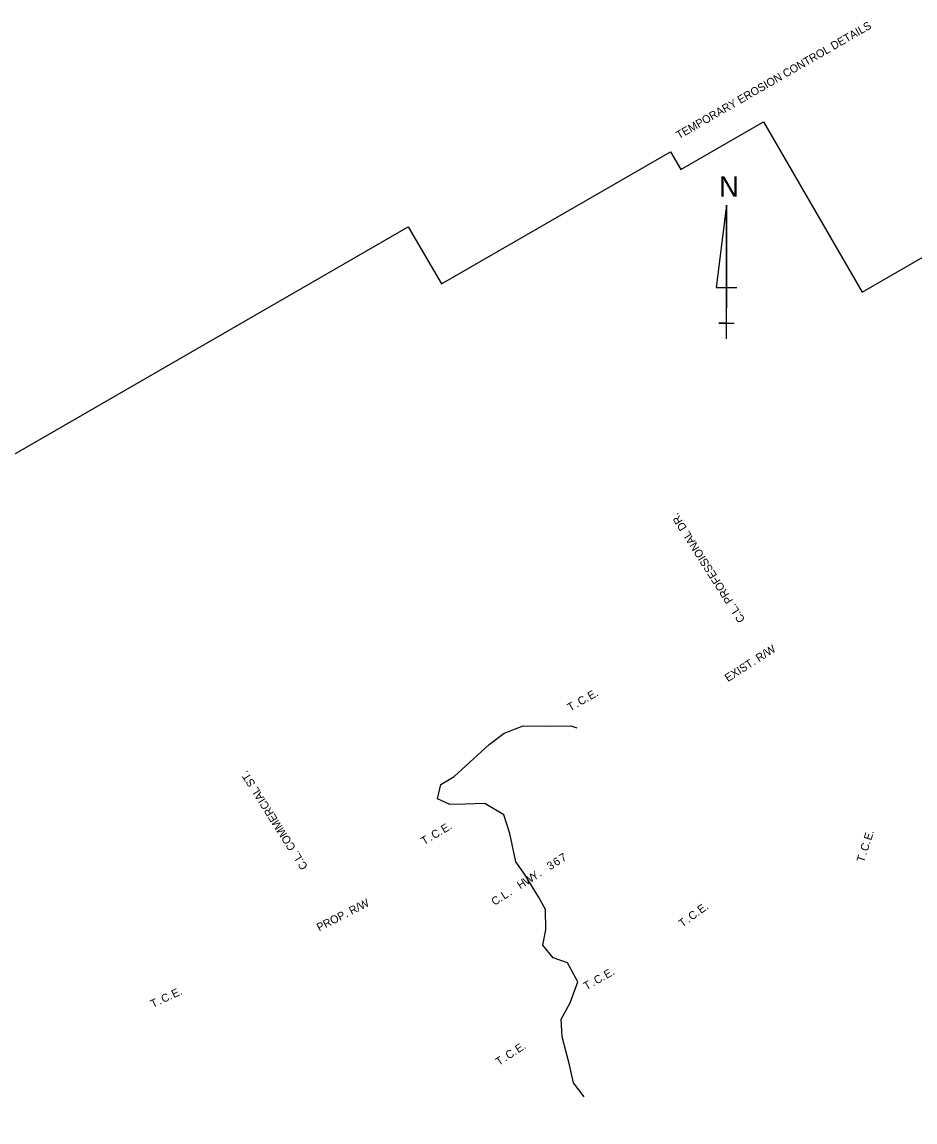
# Model space of a CAD drawing. Extents: x 1293524 to 1295623, y 222963 to 224839.
# Drawn here: x 1294272 to 1294941, y 223794 to 224618 of the extents above; entities that cross this region are included whole.
import ezdxf

# ---------------------------------------------------------------- set-up
doc = ezdxf.new("R2010")
doc.units = 0
for name, color, linetype in [('10Tan10', 7, 'Continuous'), ('Default', 7, 'Continuous'), ('G-No Plot-Border-1', 7, 'Continuous'), ('Level 1', 7, 'Continuous'), ('R_Draft', 7, 'Continuous'), ('S_TREE', 7, 'Continuous')]:
    doc.layers.add(name, color=color, linetype=linetype)

msp = doc.modelspace()

# ---------------------------------------------------------------- linework, layer by layer
at = {"layer": 'G-No Plot-Border-1'}
msp.add_lwpolyline([(1294045.04, 222962.86), (1293523.88, 223865.53), (1294561.39, 224464.54), (1294586.16, 224421.63), (1294757.85, 224520.75), (1294765.6, 224507.33), (1294827.61, 224543.13), (1294901.36, 224415.39), (1295011.78, 224479.14), (1295426.66, 223760.54)], close=True, dxfattribs=at)
msp.add_lwpolyline([(1294045.04, 222962.86), (1293523.88, 223865.53), (1294561.39, 224464.54), (1294586.16, 224421.63), (1294757.85, 224520.75), (1294765.6, 224507.33), (1294827.61, 224543.13), (1294901.36, 224415.39), (1295011.78, 224479.14), (1295426.66, 223760.54)], close=True, dxfattribs=at)
msp.add_lwpolyline([(1294045.04, 222962.86), (1293523.88, 223865.53), (1294561.39, 224464.54), (1294586.16, 224421.63), (1294757.85, 224520.75), (1294765.6, 224507.33), (1294827.61, 224543.13), (1294901.36, 224415.39), (1295011.78, 224479.14), (1295426.66, 223760.54)], close=True, dxfattribs=at)
msp.add_lwpolyline([(1294045.04, 222962.86), (1293523.88, 223865.53), (1294561.39, 224464.54), (1294586.16, 224421.63), (1294757.85, 224520.75), (1294765.6, 224507.33), (1294827.61, 224543.13), (1294901.36, 224415.39), (1295011.78, 224479.14), (1295426.66, 223760.54)], close=True, dxfattribs=at)
at = {"layer": 'Level 1'}
for p, q in [((1294799.86, 224480.59), (1294792.16, 224419.06)), ((1294799.86, 224380.59), (1294799.86, 224480.59)), ((1294799.86, 224480.59), (1294799.86, 224403.67)), ((1294792.16, 224419.06), (1294807.55, 224419.06)), ((1294799.86, 224380.59), (1294799.86, 224403.67)), ((1294799.86, 224392.13), (1294794.09, 224392.13)), ((1294794.09, 224392.13), (1294805.63, 224392.13)), ((1294799.86, 224380.59), (1294799.86, 224392.13))]:
    msp.add_line(p, q, dxfattribs=at)
at = {"layer": 'S_TREE'}
msp.add_lwpolyline([(1294693.17, 223812.27), (1294685.28, 223822.79), (1294682.25, 223836.4), (1294676.65, 223857.26), (1294675.95, 223870.53), (1294682.62, 223882.92), (1294688.42, 223898.45), (1294680.73, 223912.75), (1294669.95, 223916.58), (1294662.1, 223926.01), (1294664.35, 223937.44), (1294664.15, 223952.67), (1294658.85, 223962.28), (1294648.8, 223979.1), (1294641.85, 223988.46), (1294637.37, 224009.78), (1294632.91, 224023.68), (1294618.85, 224032.27), (1294604.15, 224031.85), (1294592.53, 224031.4), (1294583.24, 224035.85), (1294585.8, 224046.54), (1294595.63, 224052.37), (1294621.95, 224076.42), (1294633.24, 224085.05), (1294647.57, 224090.56), (1294667.83, 224090.22), (1294683.05, 224090.42), (1294687.57, 224089.02)], dxfattribs=at)

# ---------------------------------------------------------------- texts
at = {"layer": '10Tan10'}
for s, rotation, p in [('EXIST. R/W', 32.65541, (1294800.88, 224123.18)), ('PROP. R/W', 27.14839, (1294494.64, 223936.26))]:
    msp.add_text(s, height=6, rotation=rotation, dxfattribs=at).set_placement(p)
at = {"layer": 'Default'}
for s, rotation, p in [('C.L. PROFESSIONAL DR.', 122.35, (1294814.01, 224170.06)), ('C.L. COMMERCIAL ST.', 122.25, (1294486.37, 223984.84)), ('7', 32.61161, (1294676.95, 223988.05)), ('3', 32.61161, (1294667.64, 223982.09)), ('6', 32.61161, (1294672.17, 223984.99)), ('W', 32.61161, (1294649.85, 223970.71)), ('Y', 32.61161, (1294655.26, 223974.17)), ('.', 32.61161, (1294660.12, 223977.28)), ('H', 32.61161, (1294645.31, 223967.8)), ('C', 32.61161, (1294626.01, 223955.46)), ('L', 32.61161, (1294633.25, 223960.09)), ('.', 32.61161, (1294637.79, 223962.99)), ('.', 32.61161, (1294630.79, 223958.51))]:
    msp.add_text(s, height=6, rotation=rotation, dxfattribs=at).set_placement(p)
at = {"layer": 'Level 1'}
msp.add_text('N', height=15.38, rotation=360, dxfattribs=at).set_placement((1294794.22, 224487))
at = {"layer": 'R_Draft'}
for s, rotation, p in [('TEMPORARY EROSION CONTROL DETAILS', 30, (1294764.21, 224529.97)), ('C', 29.42737, (1294690.3, 224105.46)), ('E', 29.42737, (1294697.79, 224109.68)), ('.', 29.42737, (1294695.24, 224108.24)), ('.', 29.42737, (1294702.48, 224112.33)), ('T', 29.42737, (1294682.65, 224101.14)), ('.', 29.42737, (1294687.75, 224104.02)), ('C', 30.9348, (1294580.75, 224005.39)), ('E', 30.9348, (1294588.12, 224009.81)), ('.', 30.9348, (1294592.74, 224012.58)), ('E', 72.07407, (1294908.14, 224004.18)), ('.', 72.07407, (1294909.8, 224009.3)), ('T', 30.9348, (1294573.21, 224000.88)), ('.', 30.9348, (1294578.24, 224003.89)), ('.', 30.9348, (1294585.61, 224008.31)), ('C', 72.07407, (1294905.5, 223996)), ('.', 72.07407, (1294907.24, 224001.39)), ('.', 72.07407, (1294904.6, 223993.21)), ('T', 72.07407, (1294902.79, 223987.64)), ('E', 36.33859, (1294780.77, 223949.4)), ('.', 36.33859, (1294785.11, 223952.6)), ('T', 36.33859, (1294766.77, 223939.1)), ('C', 36.33859, (1294773.85, 223944.31)), ('.', 36.33859, (1294778.41, 223947.67)), ('.', 36.33859, (1294771.49, 223942.57)), ('C', 29.42737, (1294702.45, 223896.48)), ('E', 29.42737, (1294709.94, 223900.7)), ('.', 29.42737, (1294714.63, 223903.35)), ('T', 29.42737, (1294694.79, 223892.16)), ('.', 29.42737, (1294699.9, 223895.04)), ('.', 29.42737, (1294707.38, 223899.26)), ('C', 25.02866, (1294377.87, 223882.62)), ('E', 25.02866, (1294385.66, 223886.26)), ('.', 25.02866, (1294390.54, 223888.54)), ('T', 25.02866, (1294369.9, 223878.9)), ('.', 25.02866, (1294375.21, 223881.38)), ('.', 25.02866, (1294383, 223885.02)), ('C', 33.15876, (1294636.6, 223840.28)), ('E', 33.15876, (1294643.8, 223844.98)), ('.', 33.15876, (1294648.31, 223847.93)), ('T', 33.15876, (1294629.24, 223835.47)), ('.', 33.15876, (1294634.15, 223838.68)), ('.', 33.15876, (1294641.35, 223843.38))]:
    msp.add_text(s, height=6, rotation=rotation, dxfattribs=at).set_placement(p)

doc.saveas('drawing.dxf')
